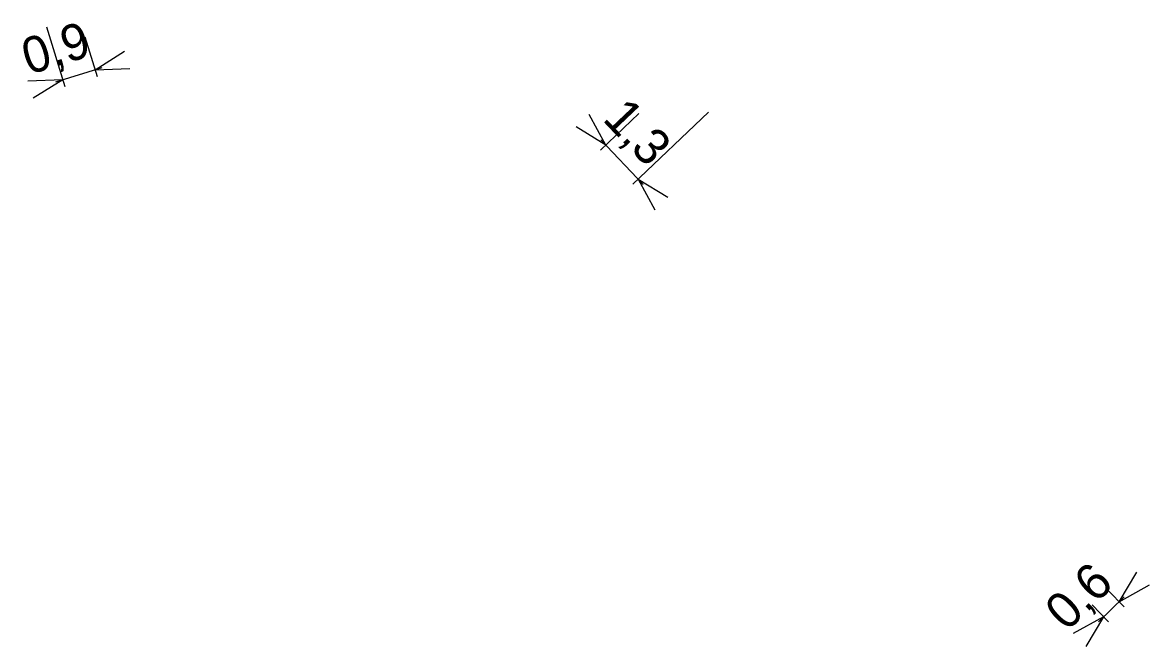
# Model space of a CAD drawing. Extents: x -739153.2 to -739122.1, y -1048408.1 to -1048390.8.
import ezdxf

# ---------------------------------------------------------------- set-up
doc = ezdxf.new("R2010")
doc.units = 0
doc.layers.add('Kota_NN', color=7, linetype='Continuous')

msp = doc.modelspace()

# ---------------------------------------------------------------- linework, layer by layer
at = {"layer": 'Kota_NN'}
for p, q in [((-739152.59, -1048390.97), (-739152.08, -1048392.62)), ((-739151.522, -1048391.242), (-739151.181, -1048392.342)), ((-739151.24, -1048392.151), (-739150.427, -1048391.64)), ((-739152.33, -1048392.488), (-739151.049, -1048392.092)), ((-739151.24, -1048392.151), (-739150.28, -1048392.115)), ((-739152.139, -1048392.429), (-739153.099, -1048392.465)), ((-739152.139, -1048392.429), (-739152.952, -1048392.94)), ((-739137.116, -1048394.237), (-739137.575, -1048393.393)), ((-739136.198, -1048393.365), (-739137.261, -1048394.375)), ((-739134.27, -1048393.33), (-739136.365, -1048395.319)), ((-739137.116, -1048394.237), (-739137.935, -1048393.735)), ((-739137.254, -1048394.092), (-739136.082, -1048395.326)), ((-739136.22, -1048395.181), (-739135.401, -1048395.683)), ((-739136.22, -1048395.181), (-739135.761, -1048396.025)), ((-739122.916, -1048406.873), (-739122.421, -1048406.05)), ((-739122.916, -1048406.873), (-739122.076, -1048406.407)), ((-739123.488, -1048407.426), (-739122.772, -1048406.734)), ((-739123.223, -1048406.555), (-739122.777, -1048407.017)), ((-739123.66, -1048406.96), (-739123.205, -1048407.431)), ((-739123.344, -1048407.287), (-739124.184, -1048407.753)), ((-739123.344, -1048407.287), (-739123.839, -1048408.11))]:
    msp.add_line(p, q, dxfattribs=at)

# ---------------------------------------------------------------- texts
for s, rotation, p in [('0,9', 17.1894, (-739153.076, -1048392.3)), ('1,3', 313.524, (-739137.232, -1048393.535)), ('0,6', 44.0197, (-739124.362, -1048407.715))]:
    msp.add_text(s, height=1, rotation=rotation, dxfattribs=at).set_placement(p)

doc.saveas('drawing.dxf')
